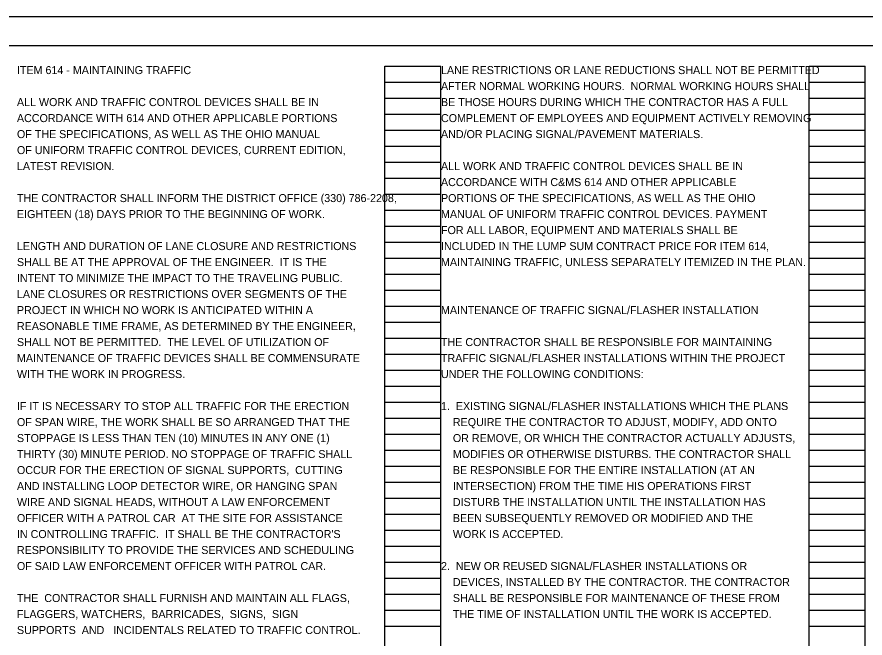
# Model space of a CAD drawing. Extents: x -6 to 34, y 0 to 22.
# Drawn here: x 2.4 to 17.24, y 11.13 to 22 of the extents above; entities that cross this region are included whole.
import ezdxf

# ---------------------------------------------------------------- set-up
doc = ezdxf.new("R2010")
doc.units = 0
for name, color, linetype in [('Default', 7, 'Continuous'), ('SH_Border', 7, 'Continuous'), ('SH_Cut_Line', 7, 'Continuous'), ('SH_Data', 7, 'Continuous'), ('SH_Text', 7, 'Continuous')]:
    doc.layers.add(name, color=color, linetype=linetype)

msp = doc.modelspace()

# ---------------------------------------------------------------- linework, layer by layer
at = {"layer": 'SH_Border'}
msp.add_lwpolyline([(1.5, 21.5), (33.5, 21.5), (33.5, 0.5), (1.5, 0.5)], close=True, dxfattribs=at)
at = {"layer": 'SH_Cut_Line'}
msp.add_lwpolyline([(0, 0), (34, 0), (34, 22), (0, 22)], close=True, dxfattribs=at)
at = {"layer": 'SH_Data'}
for p, q in [((8.84, 0.98), (8.84, 21.14)), ((8.84, 21.14), (9.82, 21.14)), ((9.82, 0.98), (9.82, 21.14)), ((16.26, 0.98), (16.26, 21.14)), ((16.26, 21.14), (17.24, 21.14)), ((17.24, 0.98), (17.24, 21.14)), ((8.84, 20.86), (9.82, 20.86)), ((16.26, 20.86), (17.24, 20.86)), ((8.84, 20.58), (9.82, 20.58)), ((16.26, 20.58), (17.24, 20.58)), ((8.84, 20.3), (9.82, 20.3)), ((16.26, 20.3), (17.24, 20.3)), ((8.84, 20.02), (9.82, 20.02)), ((16.26, 20.02), (17.24, 20.02)), ((8.84, 19.74), (9.82, 19.74)), ((16.26, 19.74), (17.24, 19.74)), ((8.84, 19.46), (9.82, 19.46)), ((16.26, 19.46), (17.24, 19.46)), ((8.84, 19.18), (9.82, 19.18)), ((16.26, 19.18), (17.24, 19.18)), ((8.84, 18.9), (9.82, 18.9)), ((16.26, 18.9), (17.24, 18.9)), ((8.84, 18.62), (9.82, 18.62)), ((16.26, 18.62), (17.24, 18.62)), ((8.84, 18.34), (9.82, 18.34)), ((16.26, 18.34), (17.24, 18.34)), ((8.84, 18.06), (9.82, 18.06)), ((16.26, 18.06), (17.24, 18.06)), ((8.84, 17.78), (9.82, 17.78)), ((16.26, 17.78), (17.24, 17.78)), ((8.84, 17.5), (9.82, 17.5)), ((16.26, 17.5), (17.24, 17.5)), ((8.84, 17.22), (9.82, 17.22)), ((16.26, 17.22), (17.24, 17.22)), ((8.84, 16.94), (9.82, 16.94)), ((16.26, 16.94), (17.24, 16.94)), ((8.84, 16.66), (9.82, 16.66)), ((16.26, 16.66), (17.24, 16.66)), ((8.84, 16.38), (9.82, 16.38)), ((16.26, 16.38), (17.24, 16.38)), ((8.84, 16.1), (9.82, 16.1)), ((16.26, 16.1), (17.24, 16.1)), ((8.84, 15.82), (9.82, 15.82)), ((16.26, 15.82), (17.24, 15.82)), ((8.84, 15.54), (9.82, 15.54)), ((16.26, 15.54), (17.24, 15.54)), ((8.84, 15.26), (9.82, 15.26)), ((16.26, 15.26), (17.24, 15.26)), ((8.84, 14.98), (9.82, 14.98)), ((16.26, 14.98), (17.24, 14.98)), ((8.84, 14.7), (9.82, 14.7)), ((16.26, 14.7), (17.24, 14.7)), ((8.84, 14.42), (9.82, 14.42)), ((16.26, 14.42), (17.24, 14.42)), ((8.84, 14.14), (9.82, 14.14)), ((16.26, 14.14), (17.24, 14.14)), ((8.84, 13.86), (9.82, 13.86)), ((16.26, 13.86), (17.24, 13.86)), ((8.84, 13.58), (9.82, 13.58)), ((16.26, 13.58), (17.24, 13.58)), ((8.84, 13.3), (9.82, 13.3)), ((16.26, 13.3), (17.24, 13.3)), ((8.84, 13.02), (9.82, 13.02)), ((16.26, 13.02), (17.24, 13.02)), ((8.84, 12.74), (9.82, 12.74)), ((16.26, 12.74), (17.24, 12.74)), ((8.84, 12.46), (9.82, 12.46)), ((16.26, 12.46), (17.24, 12.46)), ((8.84, 12.18), (9.82, 12.18)), ((16.26, 12.18), (17.24, 12.18)), ((8.84, 11.9), (9.82, 11.9)), ((16.26, 11.9), (17.24, 11.9)), ((8.84, 11.62), (9.82, 11.62)), ((16.26, 11.62), (17.24, 11.62)), ((8.84, 11.34), (9.82, 11.34)), ((16.26, 11.34), (17.24, 11.34))]:
    msp.add_line(p, q, dxfattribs=at)

# ---------------------------------------------------------------- texts
at = {"layer": 'Default'}
for s, p in [('LANE RESTRICTIONS OR LANE REDUCTIONS SHALL NOT BE PERMITTED ', (9.82, 21)), ('AFTER NORMAL WORKING HOURS.  NORMAL WORKING HOURS SHALL ', (9.82, 20.72)), ('BE THOSE HOURS DURING WHICH THE CONTRACTOR HAS A FULL ', (9.82, 20.44)), ('COMPLEMENT OF EMPLOYEES AND EQUIPMENT ACTIVELY REMOVING ', (9.82, 20.16)), ('AND/OR PLACING SIGNAL/PAVEMENT MATERIALS.', (9.82, 19.88))]:
    msp.add_text(s, height=0.14, dxfattribs=at).set_placement(p)
at = {"layer": 'SH_Text'}
for s, p in [('ITEM 614 - MAINTAINING TRAFFIC', (2.4, 21)), ('ALL WORK AND TRAFFIC CONTROL DEVICES SHALL BE IN', (2.4, 20.44)), ('ACCORDANCE WITH 614 AND OTHER APPLICABLE PORTIONS', (2.4, 20.16)), ('OF THE SPECIFICATIONS, AS WELL AS THE OHIO MANUAL', (2.4, 19.88)), ('OF UNIFORM TRAFFIC CONTROL DEVICES, CURRENT EDITION,', (2.4, 19.6)), ('LATEST REVISION.', (2.4, 19.32)), ('ALL WORK AND TRAFFIC CONTROL DEVICES SHALL BE IN', (9.82, 19.32)), ('ACCORDANCE WITH C&MS 614 AND OTHER APPLICABLE', (9.82, 19.04)), ('THE CONTRACTOR SHALL INFORM THE DISTRICT OFFICE (330) 786-2208, ', (2.4, 18.76)), ('PORTIONS OF THE SPECIFICATIONS, AS WELL AS THE OHIO', (9.82, 18.76)), ('EIGHTEEN (18) DAYS PRIOR TO THE BEGINNING OF WORK.', (2.4, 18.48)), ('MANUAL OF UNIFORM TRAFFIC CONTROL DEVICES. PAYMENT', (9.82, 18.48)), ('FOR ALL LABOR, EQUIPMENT AND MATERIALS SHALL BE', (9.82, 18.2)), ('LENGTH AND DURATION OF LANE CLOSURE AND RESTRICTIONS', (2.4, 17.92)), ('INCLUDED IN THE LUMP SUM CONTRACT PRICE FOR ITEM 614,', (9.82, 17.92)), ('SHALL BE AT THE APPROVAL OF THE ENGINEER.  IT IS THE', (2.4, 17.64)), ('MAINTAINING TRAFFIC, UNLESS SEPARATELY ITEMIZED IN THE PLAN.', (9.82, 17.64)), ('INTENT TO MINIMIZE THE IMPACT TO THE TRAVELING PUBLIC.', (2.4, 17.36)), ('LANE CLOSURES OR RESTRICTIONS OVER SEGMENTS OF THE', (2.4, 17.08)), ('PROJECT IN WHICH NO WORK IS ANTICIPATED WITHIN A', (2.4, 16.8)), ('MAINTENANCE OF TRAFFIC SIGNAL/FLASHER INSTALLATION', (9.82, 16.8)), ('REASONABLE TIME FRAME, AS DETERMINED BY THE ENGINEER,', (2.4, 16.52)), ('SHALL NOT BE PERMITTED.  THE LEVEL OF UTILIZATION OF', (2.4, 16.24)), ('THE CONTRACTOR SHALL BE RESPONSIBLE FOR MAINTAINING', (9.82, 16.24)), ('MAINTENANCE OF TRAFFIC DEVICES SHALL BE COMMENSURATE', (2.4, 15.96)), ('TRAFFIC SIGNAL/FLASHER INSTALLATIONS WITHIN THE PROJECT', (9.82, 15.96)), ('WITH THE WORK IN PROGRESS.', (2.4, 15.68)), ('UNDER THE FOLLOWING CONDITIONS:', (9.82, 15.68)), ('IF IT IS NECESSARY TO STOP ALL TRAFFIC FOR THE ERECTION', (2.4, 15.12)), ('1.  EXISTING SIGNAL/FLASHER INSTALLATIONS WHICH THE PLANS', (9.82, 15.12)), ('OF SPAN WIRE, THE WORK SHALL BE SO ARRANGED THAT THE', (2.4, 14.84)), ('    REQUIRE THE CONTRACTOR TO ADJUST, MODIFY, ADD ONTO', (9.82, 14.84)), ('STOPPAGE IS LESS THAN TEN (10) MINUTES IN ANY ONE (1)', (2.4, 14.56)), ('    OR REMOVE, OR WHICH THE CONTRACTOR ACTUALLY ADJUSTS,', (9.82, 14.56)), ('THIRTY (30) MINUTE PERIOD. NO STOPPAGE OF TRAFFIC SHALL', (2.4, 14.28)), ('    MODIFIES OR OTHERWISE DISTURBS. THE CONTRACTOR SHALL', (9.82, 14.28)), ('OCCUR FOR THE ERECTION OF SIGNAL SUPPORTS,  CUTTING', (2.4, 14)), ('    BE RESPONSIBLE FOR THE ENTIRE INSTALLATION (AT AN', (9.82, 14)), ('AND INSTALLING LOOP DETECTOR WIRE, OR HANGING SPAN', (2.4, 13.72)), ('    INTERSECTION) FROM THE TIME HIS OPERATIONS FIRST', (9.82, 13.72)), ('WIRE AND SIGNAL HEADS, WITHOUT A LAW ENFORCEMENT', (2.4, 13.44)), ('    DISTURB THE INSTALLATION UNTIL THE INSTALLATION HAS', (9.82, 13.44)), ('OFFICER WITH A PATROL CAR  AT THE SITE FOR ASSISTANCE', (2.4, 13.16)), ('    BEEN SUBSEQUENTLY REMOVED OR MODIFIED AND THE', (9.82, 13.16)), ("IN CONTROLLING TRAFFIC.  IT SHALL BE THE CONTRACTOR'S", (2.4, 12.88)), ('    WORK IS ACCEPTED.', (9.82, 12.88)), ('RESPONSIBILITY TO PROVIDE THE SERVICES AND SCHEDULING', (2.4, 12.6)), ('2.  NEW OR REUSED SIGNAL/FLASHER INSTALLATIONS OR', (9.82, 12.32)), ('OF SAID LAW ENFORCEMENT OFFICER WITH PATROL CAR.', (2.4, 12.32)), ('    DEVICES, INSTALLED BY THE CONTRACTOR. THE CONTRACTOR', (9.82, 12.04)), ('THE  CONTRACTOR SHALL FURNISH AND MAINTAIN ALL FLAGS,', (2.4, 11.76)), ('    SHALL BE RESPONSIBLE FOR MAINTENANCE OF THESE FROM', (9.82, 11.76)), ('FLAGGERS, WATCHERS,  BARRICADES,  SIGNS,  SIGN', (2.4, 11.48)), ('    THE TIME OF INSTALLATION UNTIL THE WORK IS ACCEPTED.', (9.82, 11.48)), ('SUPPORTS  AND   INCIDENTALS RELATED TO TRAFFIC CONTROL.', (2.4, 11.2))]:
    msp.add_text(s, height=0.14, dxfattribs=at).set_placement(p)

doc.saveas('drawing.dxf')
